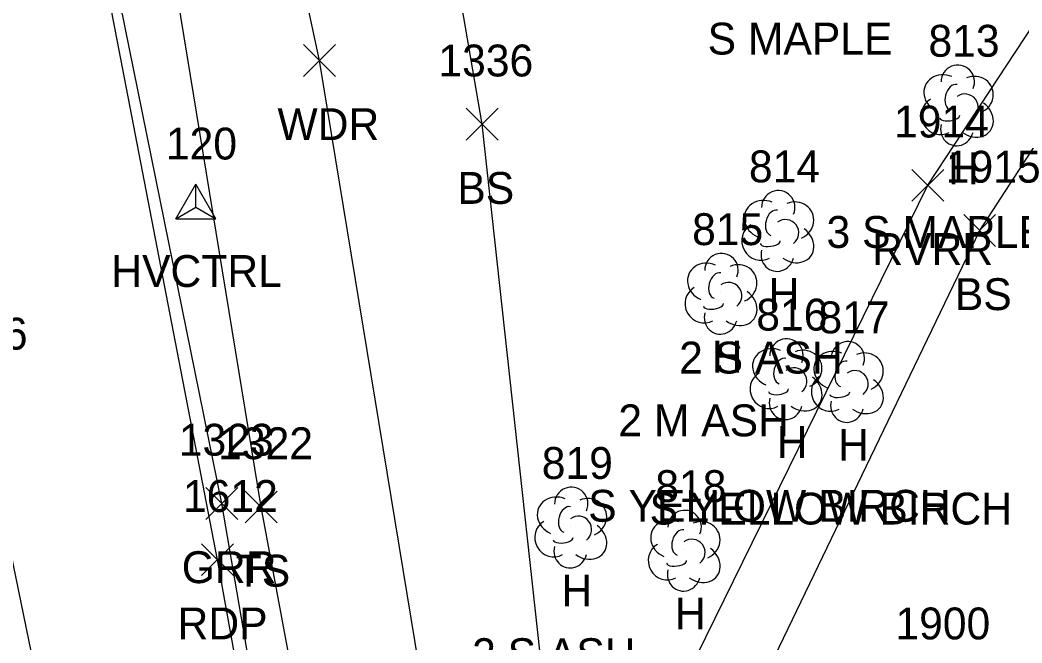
# Model space of a CAD drawing. Extents: x 1545627 to 1546562, y 571176 to 576667.
# Drawn here: x 1546104.7 to 1546167.5, y 572214.6 to 572253.7 of the extents above; entities that cross this region are included whole.
import ezdxf

# ---------------------------------------------------------------- set-up
doc = ezdxf.new("R2010")
doc.units = 0
for name, color, linetype in [('C_A', 7, 'Continuous'), ('C_I', 7, 'Continuous'), ('CPSM', 7, 'Continuous'), ('L_A', 7, 'Continuous'), ('L_C', 7, 'Continuous'), ('L_I', 7, 'Continuous'), ('L_TIC', 7, 'Continuous'), ('LAWA', 7, 'Continuous'), ('LAWE', 7, 'Continuous'), ('LELB', 7, 'Continuous'), ('LTD', 7, 'Continuous'), ('P_A', 7, 'Continuous'), ('P_I', 7, 'Continuous'), ('P_TIC', 7, 'Continuous'), ('PET', 7, 'Continuous'), ('PRC', 7, 'Continuous'), ('R_A', 7, 'Continuous'), ('R_I', 7, 'Continuous'), ('R_TIC', 7, 'Continuous'), ('RGR', 7, 'Continuous')]:
    doc.layers.add(name, color=color, linetype=linetype)

msp = doc.modelspace()

# ---------------------------------------------------------------- linework, layer by layer
at = {"layer": 'CPSM'}
for p, q in [((1546114.449, 572241.213), (1546115.699, 572243.379)), ((1546116.949, 572241.213), (1546115.699, 572243.379)), ((1546115.699, 572241.935), (1546115.699, 572243.379)), ((1546114.449, 572241.213), (1546115.699, 572241.935)), ((1546115.699, 572241.935), (1546115.699, 572241.935)), ((1546115.699, 572241.935), (1546116.949, 572241.213)), ((1546114.449, 572241.213), (1546116.949, 572241.213))]:
    msp.add_line(p, q, dxfattribs=at)
at = {"layer": 'L_TIC'}
for points in [[(1546122.453, 572250.154), (1546124.453, 572252.154)], [(1546124.453, 572250.154), (1546122.453, 572252.154)], [(1546132.659, 572246.148), (1546134.659, 572248.148)], [(1546134.659, 572246.148), (1546132.659, 572248.148)], [(1546160.621, 572242.317), (1546162.621, 572244.317)], [(1546162.621, 572242.317), (1546160.621, 572244.317)], [(1546163.869, 572239.482), (1546165.869, 572241.482)], [(1546165.869, 572239.482), (1546163.869, 572241.482)], [(1546118.789, 572222.125), (1546120.789, 572224.125)], [(1546120.789, 572222.125), (1546118.789, 572224.125)]]:
    msp.add_lwpolyline(points, dxfattribs=at)
at = {"layer": 'LAWA'}
msp.add_lwpolyline([(1546132.696, 572194.892), (1546123.453, 572251.154), (1546111.937, 572304.897), (1546099.961, 572374.277), (1546086.111, 572421.028), (1546079.849, 572451.625), (1546071.905, 572496.172), (1546064.394, 572527.582), (1546058.594, 572548.653), (1546052.091, 572585.928), (1546038.425, 572619.665), (1546027.83, 572654.921), (1546018.77, 572685.669), (1546005.342, 572728.46), (1545993.814, 572765.207), (1545980.931, 572799.992)], dxfattribs=at)
at = {"layer": 'LAWE'}
msp.add_lwpolyline([(1546079.438, 571966.947), (1546077.788, 571985.488), (1546075.176, 572034.738), (1546072.514, 572073.367), (1546072.957, 572091.545), (1546079.326, 572109.636), (1546089.965, 572133.875), (1546098.205, 572146.168), (1546103.269, 572146.803), (1546106.386, 572149.622), (1546130.143, 572181.263), (1546136.759, 572192.153), (1546140.729, 572200.768), (1546161.621, 572243.317), (1546187.565, 572282.786), (1546232.645, 572334.154), (1546255.297, 572360.235), (1546268.959, 572391.116)], dxfattribs=at)
at = {"layer": 'LELB'}
for points in [[(1546125.533, 572192.436), (1546119.789, 572223.125), (1546112.539, 572267.479), (1546101.484, 572308.512), (1546092.302, 572354.824), (1546084.689, 572391.492), (1546079.385, 572418.936), (1546072.143, 572452.753), (1546063.265, 572495.373), (1546056.178, 572525.93), (1546052.452, 572548.057), (1546043.75, 572580.7), (1546033.096, 572617.265), (1546022.592, 572652.847), (1546012.21, 572685.195), (1545999.024, 572724.088), (1545985.45, 572763.438), (1545973.138, 572794.948)], [(1546138.092, 572206.647), (1546133.659, 572247.148), (1546122.485, 572312.188), (1546113.316, 572377.356), (1546104.81, 572426.631), (1546099.996, 572460.654), (1546092.988, 572497.654), (1546081.836, 572529.538), (1546071.729, 572550.604), (1546058.937, 572584.302), (1546058.009, 572591.614), (1546041.849, 572621.011), (1546036.285, 572644.955)], [(1546140.457, 572188.687), (1546144.086, 572197.302), (1546164.869, 572240.482), (1546191.763, 572281.913), (1546238.283, 572330.782), (1546258.38, 572354.309), (1546270.264, 572391.299)]]:
    msp.add_lwpolyline(points, dxfattribs=at)
at = {"layer": 'LTD'}
for p, q in [((1546163.448, 572248.386), (1546163.448, 572248.386)), ((1546163.448, 572248.386), (1546163.448, 572248.386)), ((1546152.187, 572240.502), (1546152.187, 572240.502)), ((1546152.187, 572240.502), (1546152.187, 572240.502)), ((1546148.623, 572236.561), (1546148.623, 572236.561)), ((1546148.623, 572236.561), (1546148.623, 572236.561)), ((1546152.703, 572231.197), (1546152.703, 572231.197)), ((1546152.703, 572231.197), (1546152.703, 572231.197)), ((1546156.55, 572231.024), (1546156.55, 572231.024)), ((1546156.55, 572231.024), (1546156.55, 572231.024)), ((1546139.198, 572221.884), (1546139.198, 572221.884)), ((1546139.198, 572221.884), (1546139.198, 572221.884)), ((1546146.313, 572220.434), (1546146.313, 572220.434)), ((1546146.313, 572220.434), (1546146.313, 572220.434))]:
    msp.add_line(p, q, dxfattribs=at)
for centre in [(1546163.495, 572249.82), (1546152.234, 572241.936), (1546148.67, 572237.995), (1546152.75, 572232.631), (1546156.597, 572232.458), (1546139.245, 572223.318), (1546146.36, 572221.868)]:
    msp.add_arc(centre, 1.047, 335.52715, 180.95627, dxfattribs=at)
for centre, major_axis, ratio, start_param, end_param in [((1546162.656, 572249.052), (1.21, -0.512), 0.895232, 1.570796, 4.712389), ((1546164.49, 572248.969), (-1.141, -0.483), 0.949671, 1.570796, 4.712389), ((1546163.24, 572248.844), (-0.208, -0.792), 0.645439, 3.141593, 6.283185), ((1546162.365, 572247.677), (0.584, -1.042), 0.959034, 3.141593, 6.283185), ((1546163.948, 572248.219), (-0.5, 0.667), 0.989748, 3.141593, 6.283185), ((1546164.448, 572247.553), (-1.09, 0.792), 0.841452, 1.570796, 4.712389), ((1546162.99, 572247.636), (-0.625, -0.083), 0.423636, 0, 3.141593), ((1546163.448, 572246.886), (0.265, 1.061), 0.942809, 1.570796, 4.712389), ((1546151.396, 572241.168), (1.21, -0.512), 0.895232, 1.570796, 4.712389), ((1546153.229, 572241.085), (-1.141, -0.483), 0.949671, 1.570796, 4.712389), ((1546151.979, 572240.96), (-0.208, -0.792), 0.645439, 3.141593, 6.283185), ((1546152.688, 572240.335), (-0.5, 0.667), 0.989748, 3.141593, 6.283185), ((1546151.104, 572239.793), (0.584, -1.042), 0.959034, 3.141593, 6.283185), ((1546153.188, 572239.668), (-1.09, 0.792), 0.841452, 1.570796, 4.712389), ((1546152.188, 572239.002), (0.265, 1.061), 0.942809, 1.570796, 4.712389), ((1546151.729, 572239.751), (-0.625, -0.083), 0.423636, 0, 3.141593), ((1546147.831, 572237.228), (1.21, -0.512), 0.895232, 1.570796, 4.712389), ((1546149.665, 572237.145), (-1.141, -0.483), 0.949671, 1.570796, 4.712389), ((1546148.415, 572237.019), (-0.208, -0.792), 0.645439, 3.141593, 6.283185), ((1546149.123, 572236.394), (-0.5, 0.667), 0.989748, 3.141593, 6.283185), ((1546147.54, 572235.852), (0.584, -1.042), 0.959034, 3.141593, 6.283185), ((1546149.623, 572235.728), (-1.09, 0.792), 0.841452, 1.570796, 4.712389), ((1546148.165, 572235.811), (-0.625, -0.083), 0.423636, 0, 3.141593), ((1546148.623, 572235.061), (0.265, 1.061), 0.942809, 1.570796, 4.712389), ((1546151.912, 572231.864), (1.21, -0.512), 0.895232, 1.570796, 4.712389), ((1546153.745, 572231.781), (-1.141, -0.483), 0.949671, 1.570796, 4.712389), ((1546155.758, 572231.69), (1.21, -0.512), 0.895232, 1.570796, 4.712389), ((1546157.591, 572231.607), (-1.141, -0.483), 0.949671, 1.570796, 4.712389), ((1546152.495, 572231.656), (-0.208, -0.792), 0.645439, 3.141593, 6.283185), ((1546156.341, 572231.482), (-0.208, -0.792), 0.645439, 3.141593, 6.283185), ((1546153.203, 572231.031), (-0.5, 0.667), 0.989748, 3.141593, 6.283185), ((1546157.05, 572230.857), (-0.5, 0.667), 0.989748, 3.141593, 6.283185), ((1546151.62, 572230.489), (0.584, -1.042), 0.959034, 3.141593, 6.283185), ((1546153.704, 572230.364), (-1.09, 0.792), 0.841452, 1.570796, 4.712389), ((1546155.467, 572230.315), (0.584, -1.042), 0.959034, 3.141593, 6.283185), ((1546157.55, 572230.191), (-1.09, 0.792), 0.841452, 1.570796, 4.712389), ((1546152.245, 572230.447), (-0.625, -0.083), 0.423636, 0, 3.141593), ((1546152.704, 572229.697), (0.265, 1.061), 0.942809, 1.570796, 4.712389), ((1546156.092, 572230.274), (-0.625, -0.083), 0.423636, 0, 3.141593), ((1546156.55, 572229.524), (0.265, 1.061), 0.942809, 1.570796, 4.712389), ((1546138.406, 572222.551), (1.21, -0.512), 0.895232, 1.570796, 4.712389), ((1546140.24, 572222.467), (-1.141, -0.483), 0.949671, 1.570796, 4.712389), ((1546138.99, 572222.342), (-0.208, -0.792), 0.645439, 3.141593, 6.283185), ((1546139.698, 572221.717), (-0.5, 0.667), 0.989748, 3.141593, 6.283185), ((1546145.521, 572221.101), (1.21, -0.512), 0.895232, 1.570796, 4.712389), ((1546147.354, 572221.018), (-1.141, -0.483), 0.949671, 1.570796, 4.712389), ((1546138.115, 572221.175), (0.584, -1.042), 0.959034, 3.141593, 6.283185), ((1546140.198, 572221.051), (-1.09, 0.792), 0.841452, 1.570796, 4.712389), ((1546146.104, 572220.892), (-0.208, -0.792), 0.645439, 3.141593, 6.283185), ((1546138.74, 572221.134), (-0.625, -0.083), 0.423636, 0, 3.141593), ((1546146.813, 572220.268), (-0.5, 0.667), 0.989748, 3.141593, 6.283185), ((1546139.198, 572220.384), (0.265, 1.061), 0.942809, 1.570796, 4.712389), ((1546145.23, 572219.726), (0.584, -1.042), 0.959034, 3.141593, 6.283185), ((1546147.313, 572219.601), (-1.09, 0.792), 0.841452, 1.570796, 4.712389), ((1546145.855, 572219.684), (-0.625, -0.083), 0.423636, 0, 3.141593), ((1546146.313, 572218.934), (0.265, 1.061), 0.942809, 1.570796, 4.712389)]:
    msp.add_ellipse(centre, major_axis=major_axis, ratio=ratio, start_param=start_param, end_param=end_param, dxfattribs=at)
at = {"layer": 'P_TIC'}
for points in [[(1546116.061, 572218.813), (1546118.061, 572220.813)], [(1546118.061, 572218.813), (1546116.061, 572220.813)]]:
    msp.add_lwpolyline(points, dxfattribs=at)
at = {"layer": 'PET'}
msp.add_lwpolyline([(1546019.19, 572549.754), (1546028.198, 572511.711), (1546038.291, 572466.999), (1546043.906, 572438.712), (1546048.458, 572419.826), (1546059.016, 572375.225), (1546068.403, 572327.334), (1546078.966, 572280.941), (1546081.531, 572262.744), (1546083.99, 572253.102), (1546089.432, 572227.88), (1546096.04, 572198.55), (1546104.441, 572159.778), (1546113.192, 572174.919), (1546122.626, 572188.985), (1546117.061, 572219.813), (1546108.582, 572263.735), (1546099.519, 572308.129), (1546091.038, 572348.985), (1546082.958, 572388.468), (1546076.514, 572419.415), (1546067.661, 572461.142), (1546060.504, 572495.348), (1546051.115, 572536.864)], dxfattribs=at)
at = {"layer": 'PRC'}
msp.add_lwpolyline([(1545789.966, 573149.912), (1545812.745, 573103.838), (1545835.714, 573057.35), (1545858.015, 573011.302), (1545880.297, 572964.263), (1545901.328, 572918.696), (1545921.742, 572873.141), (1545941.501, 572826.683), (1545959.258, 572783.141), (1545976.305, 572737.153), (1545992.657, 572690.864), (1546006.775, 572646.349), (1546020.379, 572601.275), (1546032.774, 572553.215), (1546041.68, 572514.934), (1546051.794, 572470.298), (1546061.807, 572422.575), (1546071.322, 572377.997), (1546081.349, 572330.367), (1546091.011, 572283.405), (1546102.063, 572230.003), (1546107.883, 572201.699), (1546113.192, 572174.919)], dxfattribs=at)
at = {"layer": 'R_TIC'}
for points in [[(1546116.322, 572222.344), (1546118.322, 572224.344)], [(1546118.322, 572222.344), (1546116.322, 572224.344)]]:
    msp.add_lwpolyline(points, dxfattribs=at)
at = {"layer": 'RGR'}
msp.add_lwpolyline([(1546122.896, 572190.91), (1546117.322, 572223.344), (1546108.745, 572265.603), (1546099.878, 572308.896), (1546090.289, 572354.448), (1546082.741, 572391.052), (1546076.806, 572419.122), (1546069.968, 572452.166), (1546060.892, 572495.215), (1546054.251, 572525.612), (1546048.911, 572547.317), (1546040.705, 572580.212), (1546030.582, 572616.088), (1546020.216, 572652.04), (1546009.859, 572685.101), (1545996.97, 572723.718), (1545983.077, 572762.484), (1545970.878, 572794.287)], dxfattribs=at)

# ---------------------------------------------------------------- texts
at = {"layer": 'C_A'}
msp.add_text('HVCTRL', height=2, dxfattribs=at).set_placement((1546110.392, 572236.935))
at = {"layer": 'C_I'}
msp.add_text('120', height=2, dxfattribs=at).set_placement((1546113.817, 572244.935))
at = {"layer": 'L_A'}
for s, p in [('WDR', (1546120.815, 572246.154)), ('H', (1546162.881, 572243.386)), ('BS', (1546132.1, 572242.148)), ('RVRR', (1546158.132, 572238.317)), ('H', (1546151.621, 572235.502)), ('BS', (1546163.31, 572235.482)), ('H', (1546148.056, 572231.561)), ('H', (1546152.136, 572226.197)), ('H', (1546155.983, 572226.024)), ('TS', (1546118.199, 572218.125)), ('H', (1546138.631, 572216.884)), ('H', (1546145.746, 572215.434))]:
    msp.add_text(s, height=2, dxfattribs=at).set_placement(p)
at = {"layer": 'L_C'}
for s, p in [('S MAPLE', (1546147.802, 572251.524)), ('3 S MAPLE', (1546155.259, 572239.386)), ('2 S ASH', (1546146.014, 572231.502)), ('2 M ASH', (1546142.198, 572227.561)), ('S YELLOW BIRCH', (1546140.31, 572222.197)), ('S YELLOW BIRCH', (1546144.156, 572222.024)), ('2 S ASH', (1546133.025, 572212.884))]:
    msp.add_text(s, height=2, dxfattribs=at).set_placement(p)
at = {"layer": 'L_I'}
for s, p in [('813', (1546161.653, 572251.386)), ('1336', (1546130.911, 572250.148)), ('1914', (1546159.495, 572246.317)), ('814', (1546150.392, 572243.502)), ('1915', (1546162.743, 572243.482)), ('815', (1546146.828, 572239.561)), ('816', (1546150.853, 572234.197)), ('817', (1546154.754, 572234.024)), ('1322', (1546117.096, 572226.125)), ('819', (1546137.395, 572224.884)), ('818', (1546144.518, 572223.434)), ('1900', (1546159.581, 572214.813))]:
    msp.add_text(s, height=2, dxfattribs=at).set_placement(p)
at = {"layer": 'P_A'}
msp.add_text('RDP', height=2, dxfattribs=at).set_placement((1546114.549, 572214.813))
at = {"layer": 'P_I'}
for s, p in [('1606', (1546099.189, 572233.003)), ('1612', (1546114.888, 572222.813))]:
    msp.add_text(s, height=2, dxfattribs=at).set_placement(p)
at = {"layer": 'R_A'}
msp.add_text('GRR', height=2, dxfattribs=at).set_placement((1546114.811, 572218.344))
at = {"layer": 'R_I'}
msp.add_text('1323', height=2, dxfattribs=at).set_placement((1546114.629, 572226.344))

doc.saveas('drawing.dxf')
